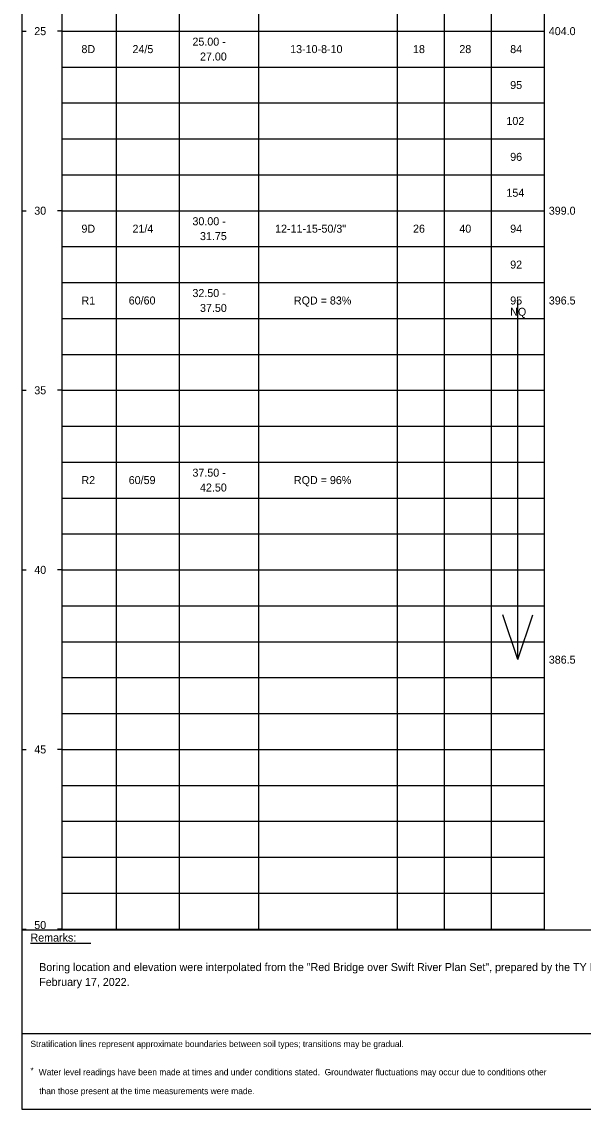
# Model space of a CAD drawing. Extents: x 9419 to 9552, y 6780 to 6865.
# Drawn here: x 9498.16 to 9513.8, y 6791.95 to 6822.23 of the extents above; entities that cross this region are included whole.
import ezdxf

# ---------------------------------------------------------------- set-up
doc = ezdxf.new("R2010")
doc.units = 0
doc.layers.add('7', color=7, linetype='Continuous')

msp = doc.modelspace()

# ---------------------------------------------------------------- linework, layer by layer
at = {"layer": '7'}
for p, q in [((9511.973, 6804.468), (9511.973, 6814.468)), ((9511.973, 6804.468), (9511.556, 6805.718)), ((9511.973, 6804.468), (9512.389, 6805.718)), ((9498.401, 6796.572), (9500.079, 6796.572))]:
    msp.add_line(p, q, dxfattribs=at)
for points in [[(9498.158, 6860.072), (9498.158, 6821.941)], [(9499.276, 6850.486), (9499.276, 6821.941)], [(9500.785, 6849.95), (9500.785, 6821.941)], [(9502.54, 6849.95), (9502.54, 6821.941)], [(9504.755, 6849.95), (9504.755, 6821.941)], [(9508.61, 6849.95), (9508.61, 6821.941)], [(9509.922, 6849.95), (9509.922, 6821.941)], [(9511.234, 6849.95), (9511.234, 6821.941)], [(9512.711, 6849.95), (9512.711, 6821.941)], [(9498.158, 6821.996), (9498.158, 6791.95)], [(9498.158, 6821.968), (9498.279, 6821.968)], [(9499.276, 6821.968), (9499.154, 6821.968)], [(9499.276, 6821.996), (9499.276, 6796.941)], [(9499.276, 6821.968), (9500.785, 6821.968)], [(9499.276, 6821.968), (9500.785, 6821.968)], [(9500.785, 6821.996), (9500.785, 6796.941)], [(9500.785, 6821.968), (9502.54, 6821.968)], [(9500.785, 6821.968), (9502.54, 6821.968)], [(9502.54, 6821.996), (9502.54, 6796.941)], [(9502.54, 6821.968), (9504.755, 6821.968)], [(9502.54, 6821.968), (9504.755, 6821.968)], [(9504.755, 6821.996), (9504.755, 6796.941)], [(9504.755, 6821.968), (9508.61, 6821.968)], [(9504.755, 6821.968), (9508.61, 6821.968)], [(9508.61, 6821.996), (9508.61, 6796.941)], [(9508.61, 6821.968), (9509.922, 6821.968)], [(9508.61, 6821.968), (9509.922, 6821.968)], [(9509.922, 6821.996), (9509.922, 6796.941)], [(9509.922, 6821.968), (9511.234, 6821.968)], [(9509.922, 6821.968), (9511.234, 6821.968)], [(9511.234, 6821.996), (9511.234, 6796.941)], [(9511.234, 6821.968), (9512.711, 6821.968)], [(9511.234, 6821.968), (9512.711, 6821.968)], [(9512.711, 6821.996), (9512.711, 6796.941)], [(9499.276, 6820.968), (9500.785, 6820.968)], [(9500.785, 6820.968), (9502.54, 6820.968)], [(9502.54, 6820.968), (9504.755, 6820.968)], [(9504.755, 6820.968), (9508.61, 6820.968)], [(9508.61, 6820.968), (9509.922, 6820.968)], [(9509.922, 6820.968), (9511.234, 6820.968)], [(9511.234, 6820.968), (9512.711, 6820.968)], [(9499.276, 6819.968), (9500.785, 6819.968)], [(9500.785, 6819.968), (9502.54, 6819.968)], [(9502.54, 6819.968), (9504.755, 6819.968)], [(9504.755, 6819.968), (9508.61, 6819.968)], [(9508.61, 6819.968), (9509.922, 6819.968)], [(9509.922, 6819.968), (9511.234, 6819.968)], [(9511.234, 6819.968), (9512.711, 6819.968)], [(9499.276, 6818.968), (9500.785, 6818.968)], [(9500.785, 6818.968), (9502.54, 6818.968)], [(9502.54, 6818.968), (9504.755, 6818.968)], [(9504.755, 6818.968), (9508.61, 6818.968)], [(9508.61, 6818.968), (9509.922, 6818.968)], [(9509.922, 6818.968), (9511.234, 6818.968)], [(9511.234, 6818.968), (9512.711, 6818.968)], [(9499.276, 6817.968), (9500.785, 6817.968)], [(9500.785, 6817.968), (9502.54, 6817.968)], [(9502.54, 6817.968), (9504.755, 6817.968)], [(9504.755, 6817.968), (9508.61, 6817.968)], [(9508.61, 6817.968), (9509.922, 6817.968)], [(9509.922, 6817.968), (9511.234, 6817.968)], [(9511.234, 6817.968), (9512.711, 6817.968)], [(9498.158, 6816.968), (9498.279, 6816.968)], [(9499.276, 6816.968), (9499.154, 6816.968)], [(9499.276, 6816.968), (9500.785, 6816.968)], [(9500.785, 6816.968), (9502.54, 6816.968)], [(9502.54, 6816.968), (9504.755, 6816.968)], [(9504.755, 6816.968), (9508.61, 6816.968)], [(9508.61, 6816.968), (9509.922, 6816.968)], [(9509.922, 6816.968), (9511.234, 6816.968)], [(9511.234, 6816.968), (9512.711, 6816.968)], [(9499.276, 6815.968), (9500.785, 6815.968)], [(9500.785, 6815.968), (9502.54, 6815.968)], [(9502.54, 6815.968), (9504.755, 6815.968)], [(9504.755, 6815.968), (9508.61, 6815.968)], [(9508.61, 6815.968), (9509.922, 6815.968)], [(9509.922, 6815.968), (9511.234, 6815.968)], [(9511.234, 6815.968), (9512.711, 6815.968)], [(9499.276, 6814.968), (9500.785, 6814.968)], [(9500.785, 6814.968), (9502.54, 6814.968)], [(9502.54, 6814.968), (9504.755, 6814.968)], [(9504.755, 6814.968), (9508.61, 6814.968)], [(9508.61, 6814.968), (9509.922, 6814.968)], [(9509.922, 6814.968), (9511.234, 6814.968)], [(9511.234, 6814.968), (9512.711, 6814.968)], [(9499.276, 6813.968), (9500.785, 6813.968)], [(9500.785, 6813.968), (9502.54, 6813.968)], [(9502.54, 6813.968), (9504.755, 6813.968)], [(9504.755, 6813.968), (9508.61, 6813.968)], [(9508.61, 6813.968), (9509.922, 6813.968)], [(9509.922, 6813.968), (9511.234, 6813.968)], [(9511.234, 6813.968), (9512.711, 6813.968)], [(9499.276, 6812.968), (9500.785, 6812.968)], [(9500.785, 6812.968), (9502.54, 6812.968)], [(9502.54, 6812.968), (9504.755, 6812.968)], [(9504.755, 6812.968), (9508.61, 6812.968)], [(9508.61, 6812.968), (9509.922, 6812.968)], [(9509.922, 6812.968), (9511.234, 6812.968)], [(9511.234, 6812.968), (9512.711, 6812.968)], [(9498.158, 6811.968), (9498.279, 6811.968)], [(9499.276, 6811.968), (9499.154, 6811.968)], [(9499.276, 6811.968), (9500.785, 6811.968)], [(9500.785, 6811.968), (9502.54, 6811.968)], [(9502.54, 6811.968), (9504.755, 6811.968)], [(9504.755, 6811.968), (9508.61, 6811.968)], [(9508.61, 6811.968), (9509.922, 6811.968)], [(9509.922, 6811.968), (9511.234, 6811.968)], [(9511.234, 6811.968), (9512.711, 6811.968)], [(9499.276, 6810.968), (9500.785, 6810.968)], [(9500.785, 6810.968), (9502.54, 6810.968)], [(9502.54, 6810.968), (9504.755, 6810.968)], [(9504.755, 6810.968), (9508.61, 6810.968)], [(9508.61, 6810.968), (9509.922, 6810.968)], [(9509.922, 6810.968), (9511.234, 6810.968)], [(9511.234, 6810.968), (9512.711, 6810.968)], [(9499.276, 6809.968), (9500.785, 6809.968)], [(9500.785, 6809.968), (9502.54, 6809.968)], [(9502.54, 6809.968), (9504.755, 6809.968)], [(9504.755, 6809.968), (9508.61, 6809.968)], [(9508.61, 6809.968), (9509.922, 6809.968)], [(9509.922, 6809.968), (9511.234, 6809.968)], [(9511.234, 6809.968), (9512.711, 6809.968)], [(9499.276, 6808.968), (9500.785, 6808.968)], [(9500.785, 6808.968), (9502.54, 6808.968)], [(9502.54, 6808.968), (9504.755, 6808.968)], [(9504.755, 6808.968), (9508.61, 6808.968)], [(9508.61, 6808.968), (9509.922, 6808.968)], [(9509.922, 6808.968), (9511.234, 6808.968)], [(9511.234, 6808.968), (9512.711, 6808.968)], [(9499.276, 6807.968), (9500.785, 6807.968)], [(9500.785, 6807.968), (9502.54, 6807.968)], [(9502.54, 6807.968), (9504.755, 6807.968)], [(9504.755, 6807.968), (9508.61, 6807.968)], [(9508.61, 6807.968), (9509.922, 6807.968)], [(9509.922, 6807.968), (9511.234, 6807.968)], [(9511.234, 6807.968), (9512.711, 6807.968)], [(9498.158, 6806.968), (9498.279, 6806.968)], [(9499.276, 6806.968), (9499.154, 6806.968)], [(9499.276, 6806.968), (9500.785, 6806.968)], [(9500.785, 6806.968), (9502.54, 6806.968)], [(9502.54, 6806.968), (9504.755, 6806.968)], [(9504.755, 6806.968), (9508.61, 6806.968)], [(9508.61, 6806.968), (9509.922, 6806.968)], [(9509.922, 6806.968), (9511.234, 6806.968)], [(9511.234, 6806.968), (9512.711, 6806.968)], [(9499.276, 6805.968), (9500.785, 6805.968)], [(9500.785, 6805.968), (9502.54, 6805.968)], [(9502.54, 6805.968), (9504.755, 6805.968)], [(9504.755, 6805.968), (9508.61, 6805.968)], [(9508.61, 6805.968), (9509.922, 6805.968)], [(9509.922, 6805.968), (9511.234, 6805.968)], [(9511.234, 6805.968), (9512.711, 6805.968)], [(9499.276, 6804.968), (9500.785, 6804.968)], [(9500.785, 6804.968), (9502.54, 6804.968)], [(9502.54, 6804.968), (9504.755, 6804.968)], [(9504.755, 6804.968), (9508.61, 6804.968)], [(9508.61, 6804.968), (9509.922, 6804.968)], [(9509.922, 6804.968), (9511.234, 6804.968)], [(9511.234, 6804.968), (9512.711, 6804.968)], [(9499.276, 6803.968), (9500.785, 6803.968)], [(9500.785, 6803.968), (9502.54, 6803.968)], [(9502.54, 6803.968), (9504.755, 6803.968)], [(9504.755, 6803.968), (9508.61, 6803.968)], [(9508.61, 6803.968), (9509.922, 6803.968)], [(9509.922, 6803.968), (9511.234, 6803.968)], [(9511.234, 6803.968), (9512.711, 6803.968)], [(9499.276, 6802.968), (9500.785, 6802.968)], [(9500.785, 6802.968), (9502.54, 6802.968)], [(9502.54, 6802.968), (9504.755, 6802.968)], [(9504.755, 6802.968), (9508.61, 6802.968)], [(9508.61, 6802.968), (9509.922, 6802.968)], [(9509.922, 6802.968), (9511.234, 6802.968)], [(9511.234, 6802.968), (9512.711, 6802.968)], [(9498.158, 6801.968), (9498.279, 6801.968)], [(9499.276, 6801.968), (9499.154, 6801.968)], [(9499.276, 6801.968), (9500.785, 6801.968)], [(9500.785, 6801.968), (9502.54, 6801.968)], [(9502.54, 6801.968), (9504.755, 6801.968)], [(9504.755, 6801.968), (9508.61, 6801.968)], [(9508.61, 6801.968), (9509.922, 6801.968)], [(9509.922, 6801.968), (9511.234, 6801.968)], [(9511.234, 6801.968), (9512.711, 6801.968)], [(9499.276, 6800.968), (9500.785, 6800.968)], [(9500.785, 6800.968), (9502.54, 6800.968)], [(9502.54, 6800.968), (9504.755, 6800.968)], [(9504.755, 6800.968), (9508.61, 6800.968)], [(9508.61, 6800.968), (9509.922, 6800.968)], [(9509.922, 6800.968), (9511.234, 6800.968)], [(9511.234, 6800.968), (9512.711, 6800.968)], [(9499.276, 6799.968), (9500.785, 6799.968)], [(9500.785, 6799.968), (9502.54, 6799.968)], [(9502.54, 6799.968), (9504.755, 6799.968)], [(9504.755, 6799.968), (9508.61, 6799.968)], [(9508.61, 6799.968), (9509.922, 6799.968)], [(9509.922, 6799.968), (9511.234, 6799.968)], [(9511.234, 6799.968), (9512.711, 6799.968)], [(9499.276, 6798.968), (9500.785, 6798.968)], [(9500.785, 6798.968), (9502.54, 6798.968)], [(9502.54, 6798.968), (9504.755, 6798.968)], [(9504.755, 6798.968), (9508.61, 6798.968)], [(9508.61, 6798.968), (9509.922, 6798.968)], [(9509.922, 6798.968), (9511.234, 6798.968)], [(9511.234, 6798.968), (9512.711, 6798.968)], [(9499.276, 6797.968), (9500.785, 6797.968)], [(9500.785, 6797.968), (9502.54, 6797.968)], [(9502.54, 6797.968), (9504.755, 6797.968)], [(9504.755, 6797.968), (9508.61, 6797.968)], [(9508.61, 6797.968), (9509.922, 6797.968)], [(9509.922, 6797.968), (9511.234, 6797.968)], [(9511.234, 6797.968), (9512.711, 6797.968)], [(9498.158, 6796.968), (9498.279, 6796.968)], [(9498.158, 6796.941), (9529.654, 6796.941)], [(9499.276, 6796.968), (9499.154, 6796.968)], [(9499.276, 6796.968), (9500.785, 6796.968)], [(9500.785, 6796.968), (9502.54, 6796.968)], [(9502.54, 6796.968), (9504.755, 6796.968)], [(9504.755, 6796.968), (9508.61, 6796.968)], [(9508.61, 6796.968), (9509.922, 6796.968)], [(9509.922, 6796.968), (9511.234, 6796.968)], [(9511.234, 6796.968), (9512.711, 6796.968)], [(9498.158, 6794.058), (9529.654, 6794.058)], [(9498.158, 6791.95), (9529.654, 6791.95)]]:
    msp.add_lwpolyline(points, dxfattribs=at)

# ---------------------------------------------------------------- texts
for s, height, p in [('25', 0.2228, (9498.507, 6821.857)), ('404.0', 0.2228, (9512.838, 6821.857)), ('8D', 0.2228, (9499.821, 6821.357)), ('24/5', 0.2228, (9501.243, 6821.357)), ('25.00 -', 0.2228, (9502.913, 6821.564)), ('13-10-8-10', 0.2228, (9505.634, 6821.357)), ('18', 0.2228, (9509.056, 6821.357)), (' 28', 0.2228, (9510.264, 6821.357)), ('84', 0.2228, (9511.763, 6821.357)), ('27.00', 0.2228, (9503.123, 6821.15)), ('95', 0.2228, (9511.763, 6820.357)), ('102', 0.2228, (9511.658, 6819.357)), ('96', 0.2228, (9511.763, 6818.357)), ('154', 0.2228, (9511.658, 6817.357)), ('30', 0.2228, (9498.507, 6816.857)), ('399.0', 0.2228, (9512.838, 6816.857)), ('30.00 -', 0.2228, (9502.913, 6816.564)), ('9D', 0.2228, (9499.821, 6816.357)), ('21/4', 0.2228, (9501.243, 6816.357)), ('31.75', 0.2228, (9503.123, 6816.15)), ('12-11-15-50/3"', 0.2228, (9505.214, 6816.357)), ('26', 0.2228, (9509.056, 6816.357)), (' 40', 0.2228, (9510.264, 6816.357)), ('94', 0.2228, (9511.763, 6816.357)), ('92', 0.2228, (9511.763, 6815.357)), ('R1', 0.2228, (9499.821, 6814.357)), ('60/60', 0.2228, (9501.138, 6814.357)), ('32.50 -', 0.2228, (9502.913, 6814.564)), ('RQD = 83%%%', 0.2228, (9505.739, 6814.357)), ('95', 0.2228, (9511.763, 6814.357)), ('396.5', 0.2228, (9512.838, 6814.357)), ('37.50', 0.2228, (9503.123, 6814.15)), ('NQ', 0.2228, (9511.763, 6814.043)), ('35', 0.2228, (9498.507, 6811.857)), ('37.50 -', 0.2228, (9502.913, 6809.564)), ('R2', 0.2228, (9499.821, 6809.357)), ('60/59', 0.2228, (9501.138, 6809.357)), ('RQD = 96%%%', 0.2228, (9505.739, 6809.357)), ('42.50', 0.2228, (9503.123, 6809.15)), ('40', 0.2228, (9498.507, 6806.857)), ('386.5', 0.2228, (9512.838, 6804.357)), ('45', 0.2228, (9498.507, 6801.857)), ('50', 0.2228, (9498.507, 6796.968)), ('Remarks:', 0.2228, (9498.401, 6796.618)), ('Boring location and elevation were interpolated from the "Red Bridge over Swift River Plan Set", prepared by the TY Lin International, last dated', 0.222801, (9498.644, 6795.797)), ('February 17, 2022.', 0.2228, (9498.644, 6795.383)), ('Stratification lines represent approximate boundaries between soil types; transitions may be gradual.', 0.175058, (9498.401, 6793.681)), ('*', 0.175, (9498.401, 6792.945)), (' Water level readings have been made at times and under conditions stated.  Groundwater fluctuations may occur due to conditions other', 0.175058, (9498.566, 6792.896)), ('than those present at the time measurements were made.', 0.17506, (9498.644, 6792.37))]:
    msp.add_text(s, height=height, dxfattribs=at).set_placement(p)

doc.saveas('drawing.dxf')
